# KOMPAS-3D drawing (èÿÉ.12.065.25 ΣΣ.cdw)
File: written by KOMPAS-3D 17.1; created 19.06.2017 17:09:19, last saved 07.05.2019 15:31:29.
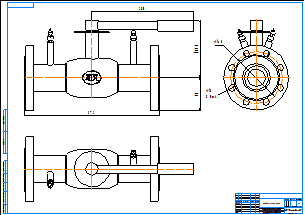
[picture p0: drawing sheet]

Sheet 1: A1, landscape

Title block, sheet 1: name: КШР.12.065.25 фф; material: Внимание! Данный продукт является объектом авторского права ООО «Торговый Дом АДЛ». / Запрещается изменение, копирование, распространение / (в том числе путем копирования на другие сайты и ресурсы в Интернете) / или любое иное использование информации и объектов без предварительного / согласия правообладателя (ООО «Торговый Дом АДЛ»).; scale: 1:1; sheets: 1; organisation: ООО "Торговый дом АДЛ"; sheet format: A1; stored path: C:\Users\tra\Desktop\2д чертежи\Шаровые краны БИВАЛ\КШР_Бивал_серия_12\KOMPAS 2D\КШР.12.065.25 фф.cdw

Views: Спереди 1, Проекционный вид 2, Проекционный вид 3
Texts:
  Klimkovich
  ADL
Dimensions and other numbers on the sheet: 372; 280; 159,3; 90; 145; 18; 8 Отв.; 1:1; 1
